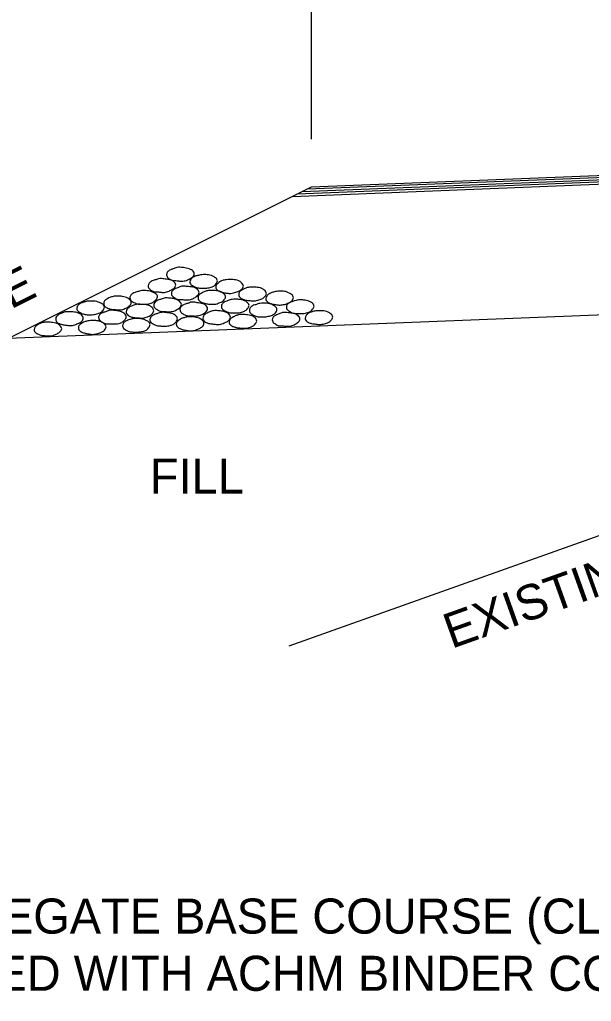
# Model space of a CAD drawing. Extents: x 634177 to 635904, y 289936 to 290970.
# Drawn here: x 635674.89 to 635684.67, y 290596.48 to 290613.28 of the extents above; entities that cross this region are included whole.
import ezdxf

# ---------------------------------------------------------------- set-up
doc = ezdxf.new("R2010")
doc.units = 0
doc.layers.add('R_Draft', color=7, linetype='Continuous')

msp = doc.modelspace()

# ---------------------------------------------------------------- linework, layer by layer
at = {"layer": 'R_Draft'}
for p, q in [((635679.883, 290611.232), (635679.883, 290626.512)), ((635679.808, 290610.381), (635744.062, 290612.944)), ((635679.883, 290610.417), (635743.993, 290612.978)), ((635679.556, 290610.253), (635744.281, 290612.835)), ((635679.64, 290610.297), (635744.208, 290612.871)), ((635679.723, 290610.336), (635744.137, 290612.908)), ((635667.465, 290604.212), (635679.883, 290610.417)), ((635674.699, 290607.826), (635699.814, 290608.826)), ((635694.262, 290607.831), (635679.497, 290602.555))]:
    msp.add_line(p, q, dxfattribs=at)
for points in [[(635677.635, 290609.041), (635677.718, 290609.031), (635677.817, 290609.003), (635677.871, 290608.959), (635677.878, 290608.929), (635677.853, 290608.879), (635677.821, 290608.855), (635677.764, 290608.824), (635677.686, 290608.804), (635677.644, 290608.804), (635677.584, 290608.811), (635677.512, 290608.815), (635677.462, 290608.836), (635677.413, 290608.882), (635677.407, 290608.913), (635677.421, 290608.96), (635677.458, 290608.989), (635677.493, 290609.006), (635677.549, 290609.024), (635677.581, 290609.038), (635677.635, 290609.041)], [(635678.036, 290608.916), (635678.121, 290608.91), (635678.219, 290608.877), (635678.267, 290608.834), (635678.274, 290608.809), (635678.249, 290608.754), (635678.226, 290608.728), (635678.168, 290608.7), (635678.091, 290608.685), (635678.048, 290608.682), (635677.986, 290608.683), (635677.915, 290608.694), (635677.864, 290608.719), (635677.812, 290608.758), (635677.804, 290608.791), (635677.818, 290608.834), (635677.859, 290608.871), (635677.893, 290608.887), (635677.95, 290608.902), (635677.984, 290608.91), (635678.036, 290608.916)], [(635677.319, 290608.847), (635677.404, 290608.836), (635677.5, 290608.813), (635677.554, 290608.766), (635677.562, 290608.737), (635677.535, 290608.686), (635677.504, 290608.664), (635677.449, 290608.634), (635677.369, 290608.611), (635677.328, 290608.611), (635677.267, 290608.618), (635677.196, 290608.622), (635677.145, 290608.644), (635677.098, 290608.69), (635677.089, 290608.721), (635677.106, 290608.766), (635677.143, 290608.799), (635677.178, 290608.815), (635677.233, 290608.833), (635677.267, 290608.844), (635677.319, 290608.847)], [(635678.477, 290608.83), (635678.559, 290608.828), (635678.662, 290608.796), (635678.709, 290608.747), (635678.718, 290608.719), (635678.69, 290608.667), (635678.664, 290608.644), (635678.609, 290608.62), (635678.528, 290608.597), (635678.484, 290608.594), (635678.422, 290608.6), (635678.355, 290608.611), (635678.303, 290608.632), (635678.253, 290608.672), (635678.245, 290608.703), (635678.262, 290608.749), (635678.299, 290608.778), (635678.334, 290608.804), (635678.389, 290608.821), (635678.424, 290608.828), (635678.477, 290608.83)], [(635677.011, 290608.644), (635677.094, 290608.636), (635677.191, 290608.606), (635677.242, 290608.564), (635677.25, 290608.534), (635677.222, 290608.484), (635677.193, 290608.457), (635677.142, 290608.427), (635677.062, 290608.41), (635677.021, 290608.41), (635676.957, 290608.408), (635676.887, 290608.419), (635676.834, 290608.444), (635676.785, 290608.488), (635676.779, 290608.515), (635676.793, 290608.566), (635676.829, 290608.594), (635676.868, 290608.611), (635676.926, 290608.629), (635676.957, 290608.639), (635677.011, 290608.644)], [(635677.721, 290608.717), (635677.804, 290608.707), (635677.904, 290608.683), (635677.953, 290608.635), (635677.96, 290608.607), (635677.936, 290608.555), (635677.906, 290608.533), (635677.853, 290608.502), (635677.774, 290608.483), (635677.731, 290608.483), (635677.668, 290608.488), (635677.598, 290608.491), (635677.547, 290608.516), (635677.497, 290608.56), (635677.488, 290608.591), (635677.504, 290608.638), (635677.542, 290608.666), (635677.58, 290608.683), (635677.635, 290608.704), (635677.668, 290608.716), (635677.721, 290608.717)], [(635678.176, 290608.643), (635678.258, 290608.639), (635678.36, 290608.609), (635678.407, 290608.561), (635678.414, 290608.533), (635678.389, 290608.481), (635678.365, 290608.458), (635678.306, 290608.431), (635678.229, 290608.408), (635678.186, 290608.408), (635678.122, 290608.412), (635678.054, 290608.424), (635678.003, 290608.442), (635677.951, 290608.486), (635677.944, 290608.517), (635677.957, 290608.564), (635677.997, 290608.593), (635678.033, 290608.612), (635678.089, 290608.635), (635678.122, 290608.642), (635678.176, 290608.643)], [(635678.873, 290608.702), (635678.959, 290608.697), (635679.056, 290608.666), (635679.104, 290608.62), (635679.112, 290608.589), (635679.085, 290608.54), (635679.063, 290608.517), (635679.004, 290608.491), (635678.925, 290608.466), (635678.884, 290608.466), (635678.821, 290608.471), (635678.755, 290608.479), (635678.698, 290608.499), (635678.647, 290608.543), (635678.639, 290608.574), (635678.655, 290608.621), (635678.692, 290608.65), (635678.731, 290608.672), (635678.786, 290608.693), (635678.821, 290608.699), (635678.873, 290608.702)], [(635679.336, 290608.631), (635679.42, 290608.629), (635679.516, 290608.594), (635679.565, 290608.551), (635679.573, 290608.522), (635679.549, 290608.468), (635679.521, 290608.446), (635679.467, 290608.419), (635679.386, 290608.398), (635679.345, 290608.394), (635679.283, 290608.4), (635679.214, 290608.411), (635679.159, 290608.431), (635679.109, 290608.471), (635679.101, 290608.504), (635679.117, 290608.549), (635679.154, 290608.582), (635679.193, 290608.604), (635679.248, 290608.621), (635679.284, 290608.629), (635679.336, 290608.631)], [(635676.104, 290608.462), (635676.187, 290608.458), (635676.284, 290608.424), (635676.336, 290608.383), (635676.343, 290608.356), (635676.315, 290608.301), (635676.29, 290608.274), (635676.232, 290608.25), (635676.156, 290608.231), (635676.116, 290608.227), (635676.049, 290608.229), (635675.978, 290608.242), (635675.929, 290608.265), (635675.879, 290608.305), (635675.871, 290608.335), (635675.886, 290608.383), (635675.923, 290608.416), (635675.961, 290608.432), (635676.017, 290608.451), (635676.049, 290608.458), (635676.104, 290608.462)], [(635676.563, 290608.547), (635676.649, 290608.542), (635676.745, 290608.511), (635676.794, 290608.464), (635676.8, 290608.436), (635676.776, 290608.386), (635676.749, 290608.362), (635676.694, 290608.334), (635676.615, 290608.312), (635676.573, 290608.312), (635676.51, 290608.318), (635676.443, 290608.325), (635676.389, 290608.344), (635676.337, 290608.389), (635676.331, 290608.421), (635676.345, 290608.466), (635676.382, 290608.496), (635676.419, 290608.517), (635676.478, 290608.537), (635676.51, 290608.545), (635676.563, 290608.547)], [(635676.947, 290608.407), (635677.028, 290608.401), (635677.129, 290608.373), (635677.179, 290608.324), (635677.186, 290608.296), (635677.161, 290608.246), (635677.136, 290608.222), (635677.077, 290608.195), (635677.001, 290608.172), (635676.955, 290608.172), (635676.892, 290608.176), (635676.823, 290608.186), (635676.772, 290608.205), (635676.721, 290608.25), (635676.714, 290608.28), (635676.73, 290608.326), (635676.768, 290608.356), (635676.804, 290608.377), (635676.86, 290608.398), (635676.892, 290608.405), (635676.947, 290608.407)], [(635677.415, 290608.516), (635677.499, 290608.508), (635677.6, 290608.478), (635677.65, 290608.432), (635677.659, 290608.405), (635677.632, 290608.353), (635677.605, 290608.331), (635677.546, 290608.297), (635677.47, 290608.28), (635677.426, 290608.28), (635677.363, 290608.282), (635677.294, 290608.289), (635677.242, 290608.316), (635677.193, 290608.357), (635677.186, 290608.39), (635677.202, 290608.436), (635677.24, 290608.466), (635677.276, 290608.483), (635677.328, 290608.499), (635677.362, 290608.511), (635677.415, 290608.516)], [(635677.868, 290608.444), (635677.951, 290608.432), (635678.048, 290608.407), (635678.097, 290608.36), (635678.105, 290608.331), (635678.079, 290608.28), (635678.054, 290608.257), (635677.997, 290608.227), (635677.919, 290608.207), (635677.876, 290608.207), (635677.814, 290608.211), (635677.743, 290608.216), (635677.69, 290608.242), (635677.641, 290608.285), (635677.634, 290608.318), (635677.647, 290608.361), (635677.685, 290608.391), (635677.724, 290608.41), (635677.782, 290608.428), (635677.814, 290608.441), (635677.868, 290608.444)], [(635678.579, 290608.496), (635678.664, 290608.489), (635678.758, 290608.458), (635678.807, 290608.414), (635678.815, 290608.388), (635678.791, 290608.333), (635678.764, 290608.309), (635678.707, 290608.279), (635678.627, 290608.26), (635678.587, 290608.26), (635678.525, 290608.262), (635678.456, 290608.27), (635678.402, 290608.296), (635678.35, 290608.337), (635678.342, 290608.373), (635678.359, 290608.416), (635678.396, 290608.447), (635678.433, 290608.462), (635678.489, 290608.481), (635678.528, 290608.492), (635678.579, 290608.496)], [(635679.054, 290608.427), (635679.137, 290608.423), (635679.236, 290608.389), (635679.285, 290608.346), (635679.292, 290608.32), (635679.267, 290608.263), (635679.243, 290608.239), (635679.184, 290608.212), (635679.106, 290608.195), (635679.065, 290608.191), (635679.002, 290608.191), (635678.93, 290608.204), (635678.88, 290608.229), (635678.83, 290608.267), (635678.821, 290608.301), (635678.837, 290608.346), (635678.873, 290608.381), (635678.913, 290608.396), (635678.968, 290608.414), (635679, 290608.423), (635679.054, 290608.427)], [(635679.692, 290608.486), (635679.775, 290608.476), (635679.871, 290608.446), (635679.92, 290608.401), (635679.926, 290608.374), (635679.903, 290608.322), (635679.878, 290608.296), (635679.82, 290608.265), (635679.739, 290608.25), (635679.699, 290608.25), (635679.637, 290608.252), (635679.568, 290608.257), (635679.513, 290608.284), (635679.462, 290608.326), (635679.455, 290608.358), (635679.469, 290608.404), (635679.508, 290608.434), (635679.546, 290608.451), (635679.601, 290608.468), (635679.64, 290608.479), (635679.692, 290608.486)], [(635675.742, 290608.28), (635675.824, 290608.275), (635675.925, 290608.246), (635675.973, 290608.197), (635675.981, 290608.17), (635675.956, 290608.117), (635675.93, 290608.095), (635675.874, 290608.071), (635675.795, 290608.045), (635675.752, 290608.045), (635675.688, 290608.05), (635675.619, 290608.062), (635675.567, 290608.079), (635675.517, 290608.122), (635675.511, 290608.155), (635675.524, 290608.2), (635675.564, 290608.23), (635675.601, 290608.252), (635675.656, 290608.271), (635675.688, 290608.279), (635675.742, 290608.28)], [(635676.481, 290608.305), (635676.562, 290608.296), (635676.658, 290608.265), (635676.708, 290608.222), (635676.714, 290608.193), (635676.692, 290608.143), (635676.664, 290608.115), (635676.61, 290608.086), (635676.527, 290608.071), (635676.486, 290608.071), (635676.422, 290608.072), (635676.353, 290608.078), (635676.301, 290608.102), (635676.252, 290608.148), (635676.242, 290608.179), (635676.258, 290608.225), (635676.294, 290608.254), (635676.334, 290608.27), (635676.39, 290608.288), (635676.425, 290608.3), (635676.481, 290608.305)], [(635677.356, 290608.27), (635677.438, 290608.26), (635677.535, 290608.231), (635677.584, 290608.187), (635677.591, 290608.16), (635677.568, 290608.109), (635677.542, 290608.081), (635677.486, 290608.051), (635677.406, 290608.034), (635677.363, 290608.034), (635677.3, 290608.036), (635677.233, 290608.044), (635677.179, 290608.071), (635677.127, 290608.111), (635677.119, 290608.146), (635677.136, 290608.189), (635677.174, 290608.22), (635677.211, 290608.237), (635677.267, 290608.254), (635677.302, 290608.265), (635677.356, 290608.27)], [(635678.26, 290608.299), (635678.343, 290608.292), (635678.442, 290608.26), (635678.489, 290608.216), (635678.497, 290608.186), (635678.47, 290608.136), (635678.448, 290608.113), (635678.391, 290608.088), (635678.312, 290608.062), (635678.269, 290608.062), (635678.206, 290608.069), (635678.138, 290608.077), (635678.085, 290608.095), (635678.032, 290608.14), (635678.025, 290608.172), (635678.041, 290608.216), (635678.079, 290608.248), (635678.117, 290608.267), (635678.173, 290608.288), (635678.206, 290608.296), (635678.26, 290608.299)], [(635678.706, 290608.231), (635678.791, 290608.227), (635678.891, 290608.196), (635678.939, 290608.149), (635678.947, 290608.12), (635678.922, 290608.071), (635678.897, 290608.047), (635678.839, 290608.018), (635678.761, 290607.998), (635678.719, 290607.998), (635678.655, 290608.002), (635678.585, 290608.013), (635678.535, 290608.03), (635678.482, 290608.074), (635678.476, 290608.106), (635678.49, 290608.15), (635678.53, 290608.181), (635678.566, 290608.201), (635678.621, 290608.224), (635678.655, 290608.23), (635678.706, 290608.231)], [(635679.441, 290608.267), (635679.528, 290608.258), (635679.625, 290608.233), (635679.677, 290608.185), (635679.686, 290608.158), (635679.66, 290608.106), (635679.632, 290608.083), (635679.572, 290608.051), (635679.496, 290608.032), (635679.454, 290608.032), (635679.391, 290608.038), (635679.319, 290608.041), (635679.269, 290608.068), (635679.221, 290608.11), (635679.213, 290608.143), (635679.228, 290608.187), (635679.265, 290608.217), (635679.3, 290608.234), (635679.358, 290608.254), (635679.39, 290608.267), (635679.441, 290608.267)], [(635680.009, 290608.297), (635680.092, 290608.295), (635680.19, 290608.259), (635680.238, 290608.217), (635680.246, 290608.188), (635680.222, 290608.135), (635680.194, 290608.111), (635680.142, 290608.086), (635680.059, 290608.065), (635680.018, 290608.062), (635679.957, 290608.068), (635679.886, 290608.078), (635679.832, 290608.097), (635679.782, 290608.139), (635679.775, 290608.17), (635679.79, 290608.216), (635679.827, 290608.25), (635679.866, 290608.27), (635679.923, 290608.288), (635679.958, 290608.295), (635680.009, 290608.297)], [(635675.372, 290608.102), (635675.46, 290608.095), (635675.556, 290608.068), (635675.604, 290608.018), (635675.612, 290607.992), (635675.587, 290607.941), (635675.562, 290607.919), (635675.505, 290607.891), (635675.426, 290607.866), (635675.384, 290607.866), (635675.321, 290607.871), (635675.253, 290607.879), (635675.201, 290607.901), (635675.149, 290607.943), (635675.141, 290607.976), (635675.157, 290608.02), (635675.193, 290608.051), (635675.23, 290608.074), (635675.288, 290608.093), (635675.321, 290608.099), (635675.372, 290608.102)], [(635676.133, 290608.131), (635676.216, 290608.127), (635676.313, 290608.093), (635676.36, 290608.05), (635676.37, 290608.02), (635676.345, 290607.967), (635676.318, 290607.943), (635676.265, 290607.919), (635676.184, 290607.897), (635676.141, 290607.892), (635676.078, 290607.9), (635676.011, 290607.912), (635675.956, 290607.933), (635675.905, 290607.971), (635675.897, 290608.004), (635675.912, 290608.048), (635675.951, 290608.081), (635675.988, 290608.102), (635676.043, 290608.119), (635676.08, 290608.127), (635676.133, 290608.131)], [(635676.885, 290608.165), (635676.968, 290608.16), (635677.07, 290608.126), (635677.117, 290608.085), (635677.123, 290608.06), (635677.099, 290608.004), (635677.075, 290607.976), (635677.015, 290607.948), (635676.938, 290607.934), (635676.896, 290607.932), (635676.834, 290607.933), (635676.762, 290607.942), (635676.712, 290607.967), (635676.661, 290608.008), (635676.653, 290608.039), (635676.669, 290608.085), (635676.706, 290608.117), (635676.744, 290608.135), (635676.798, 290608.152), (635676.832, 290608.16), (635676.885, 290608.165)], [(635677.807, 290608.191), (635677.888, 290608.188), (635677.989, 290608.155), (635678.036, 290608.111), (635678.045, 290608.083), (635678.02, 290608.028), (635677.992, 290608.008), (635677.94, 290607.981), (635677.859, 290607.957), (635677.815, 290607.953), (635677.752, 290607.96), (635677.685, 290607.972), (635677.631, 290607.994), (635677.58, 290608.032), (635677.572, 290608.065), (635677.588, 290608.11), (635677.627, 290608.144), (635677.663, 290608.165), (635677.72, 290608.181), (635677.753, 290608.188), (635677.807, 290608.191)]]:
    msp.add_spline(points, degree=3, dxfattribs=at)

# ---------------------------------------------------------------- texts
for s, rotation, p in [('DESIGN SLOPE', 26.565, (635669.876, 290605.883)), ('EXISTING SLOPE', 19.6609, (635682.277, 290602.509))]:
    msp.add_text(s, height=0.6, rotation=rotation, dxfattribs=at).set_placement(p)
for s, p in [('FILL', (635677.12, 290605.167)), ('* 7" AGGREGATE BASE COURSE (CLASS 7)', (635670.739, 290597.638)), ('TO BE REPLACED WITH ACHM BINDER COURSE (1")', (635668.639, 290596.659))]:
    msp.add_text(s, height=0.6, dxfattribs=at).set_placement(p)

doc.saveas('drawing.dxf')
